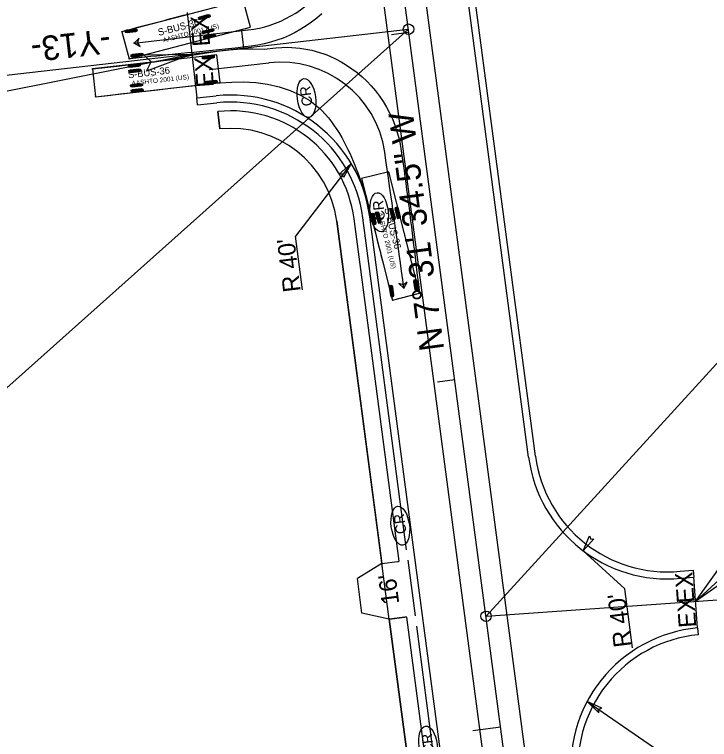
# Model space of a CAD drawing. Extents: x 2367848 to 2369479, y 800728 to 808616.
# Drawn here: x 2368456 to 2368654.5, y 806311.1 to 806518.1 of the extents above; entities that cross this region are included whole.
import ezdxf

# ---------------------------------------------------------------- set-up
doc = ezdxf.new("R2010")
doc.units = 0
for name, color, linetype in [('Prop AutoTurn Projected Path', 7, 'Continuous'), ('Prop AutoTurn Simulation', 7, 'Continuous'), ('Prop Conc 2ft 6in Curb and Gutter', 7, 'Continuous'), ('Prop Conc 4in Sidewalk', 7, 'Continuous'), ('Prop Conc Drive Radius Type', 7, 'Continuous'), ('Prop Conc Driveway', 7, 'Continuous'), ('Prop Dimension', 7, 'Continuous'), ('Prop EOT', 7, 'Continuous'), ('Prop Horizontal Alignment', 7, 'Continuous'), ('Prop Horizontal Alignment Direction Label', 7, 'Continuous'), ('Prop Horizontal Alignment Station Label', 7, 'Continuous'), ('Prop Horizontal Alignment Tick Large', 7, 'Continuous'), ('Prop Horizontal Alignment Tick Small', 7, 'Continuous'), ('Prop Lane Lines', 7, 'Continuous'), ('Prop Shade Light', 7, 'Continuous'), ('Prop Terminator CELL', 7, 'Continuous'), ('Prop WCC CELL', 7, 'Continuous'), ('Prop WCR CELL', 7, 'Continuous')]:
    doc.layers.add(name, color=color, linetype=linetype)

# ---------------------------------------------------------------- blocks, each defined once
blk = doc.blocks.new('CR')
at = {"layer": 'Prop WCC CELL'}
blk.add_ellipse((0.02, -0.02), major_axis=(5.61, 0), ratio=0.462467, dxfattribs=at)
blk.add_text('CR', height=3, dxfattribs=at).set_placement((-2.34, -1.5))

msp = doc.modelspace()

# ---------------------------------------------------------------- linework, layer by layer
at = {"layer": 'Prop AutoTurn Projected Path'}
for p, q in [((2368490.13, 806509.94), (2368522.7, 806513.66)), ((2368511.76, 806502.35), (2368528.64, 806504.28))]:
    msp.add_line(p, q, dxfattribs=at)
for centre, radius, start, end in [((2368519.07, 806545.46), 32, 276.5258, 9.3013), ((2368532.05, 806474.47), 30, 8.2571, 96.5258), ((2364614.09, 805905.9), 3989, 7.69347, 8.25707)]:
    msp.add_arc(centre, radius, start, end, dxfattribs=at)
at = {"layer": 'Prop AutoTurn Simulation'}
for p, q in [((2368521.32, 806522.25), (2368486.69, 806513.17)), ((2368523.35, 806514.51), (2368521.32, 806522.25)), ((2368508.54, 806517.13), (2368511.76, 806517.98)), ((2368508.59, 806516.93), (2368511.81, 806517.78)), ((2368508.64, 806516.73), (2368511.87, 806517.58)), ((2368487.6, 806513.44), (2368490.91, 806513.81)), ((2368488.72, 806505.43), (2368523.35, 806514.51)), ((2368509.59, 806513.1), (2368512.82, 806513.95)), ((2368486.69, 806513.17), (2368488.72, 806505.43)), ((2368487.62, 806513.23), (2368490.93, 806513.6)), ((2368487.64, 806513.02), (2368490.96, 806513.39)), ((2368509.65, 806512.9), (2368512.87, 806513.75)), ((2368509.7, 806512.7), (2368512.92, 806513.55)), ((2368509.97, 806511.65), (2368513.2, 806512.5)), ((2368510.03, 806511.45), (2368513.25, 806512.3)), ((2368510.08, 806511.25), (2368513.3, 806512.09)), ((2368513.79, 806506.61), (2368478.22, 806502.54)), ((2368489.3, 806506.47), (2368492.61, 806506.86)), ((2368489.32, 806506.27), (2368492.63, 806506.66)), ((2368489.35, 806506.06), (2368492.66, 806506.45)), ((2368512.99, 806506.3), (2368509.68, 806505.93)), ((2368513.01, 806506.1), (2368509.7, 806505.72)), ((2368513.03, 806505.89), (2368509.72, 806505.51)), ((2368514.7, 806498.66), (2368513.79, 806506.61)), ((2368513.79, 806506.61), (2368513.79, 806506.61)), ((2368491.83, 806503.88), (2368488.51, 806503.5)), ((2368491.85, 806503.68), (2368488.54, 806503.3)), ((2368491.87, 806503.47), (2368488.56, 806503.09)), ((2368488.72, 806505.43), (2368488.72, 806505.43)), ((2368478.22, 806502.54), (2368479.13, 806494.59)), ((2368492, 806502.39), (2368488.68, 806502.01)), ((2368492.02, 806502.19), (2368488.71, 806501.81)), ((2368492.04, 806501.98), (2368488.73, 806501.6)), ((2368479.13, 806494.59), (2368514.7, 806498.66)), ((2368492.47, 806498.25), (2368489.16, 806497.87)), ((2368492.49, 806498.05), (2368489.18, 806497.67)), ((2368492.52, 806497.84), (2368489.2, 806497.46)), ((2368513.8, 806499.18), (2368510.49, 806498.81)), ((2368513.83, 806498.98), (2368510.51, 806498.6)), ((2368513.85, 806498.77), (2368510.54, 806498.39)), ((2368492.64, 806496.76), (2368489.33, 806496.38)), ((2368492.66, 806496.56), (2368489.35, 806496.18)), ((2368492.69, 806496.35), (2368489.38, 806495.97)), ((2368562.88, 806473.18), (2368555.13, 806471.22)), ((2368571.68, 806438.48), (2368562.88, 806473.18)), ((2368555.13, 806471.22), (2368563.92, 806436.52)), ((2368564.18, 806459.41), (2368563.36, 806462.65)), ((2368564.38, 806459.47), (2368563.56, 806462.7)), ((2368564.58, 806459.52), (2368563.77, 806462.75)), ((2368565.63, 806459.78), (2368564.82, 806463.01)), ((2368565.84, 806459.83), (2368565.02, 806463.07)), ((2368566.04, 806459.89), (2368565.22, 806463.12)), ((2368558.69, 806458.02), (2368557.87, 806461.25)), ((2368558.89, 806458.07), (2368558.07, 806461.3)), ((2368559.09, 806458.12), (2368558.27, 806461.36)), ((2368560.14, 806458.39), (2368559.32, 806461.62)), ((2368560.34, 806458.44), (2368559.52, 806461.67)), ((2368560.55, 806458.49), (2368559.73, 806461.72)), ((2368570.69, 806439.08), (2368570.24, 806442.38)), ((2368570.9, 806439.11), (2368570.44, 806442.41)), ((2368571.1, 806439.13), (2368570.65, 806442.44)), ((2368563.72, 806437.41), (2368563.28, 806440.71)), ((2368563.92, 806437.44), (2368563.48, 806440.74)), ((2368564.13, 806437.46), (2368563.69, 806440.77)), ((2368563.92, 806436.52), (2368571.68, 806438.48)), ((2368571.68, 806438.48), (2368571.68, 806438.48))]:
    msp.add_line(p, q, dxfattribs=at)
for points in [[(2368505.55, 806518.12), (2368504.14, 806517.75), (2368502.71, 806517.37), (2368501.27, 806516.99), (2368499.8, 806516.61), (2368498.32, 806516.22), (2368496.82, 806515.83), (2368495.31, 806515.43), (2368493.79, 806515.03), (2368492.26, 806514.63), (2368490.73, 806514.23), (2368489.18, 806513.83), (2368487.63, 806513.42), (2368486.69, 806513.17)], [(2368543.74, 806518.27), (2368542.33, 806517.05), (2368540.86, 806515.91), (2368539.33, 806514.84), (2368537.75, 806513.85), (2368536.11, 806512.94), (2368534.43, 806512.11), (2368532.7, 806511.37), (2368530.94, 806510.72), (2368529.14, 806510.16), (2368527.32, 806509.69), (2368525.47, 806509.31), (2368523.6, 806509.03), (2368521.73, 806508.81), (2368519.87, 806508.59), (2368518.02, 806508.39), (2368516.19, 806508.19), (2368514.36, 806508), (2368512.55, 806507.81), (2368510.75, 806507.63), (2368508.96, 806507.45), (2368507.17, 806507.27), (2368505.4, 806507.1), (2368503.63, 806506.92), (2368501.88, 806506.75), (2368500.13, 806506.58), (2368498.38, 806506.4), (2368496.65, 806506.23), (2368494.91, 806506.06), (2368493.19, 806505.89), (2368491.47, 806505.71), (2368489.75, 806505.54), (2368488.72, 806505.43)], [(2368478.22, 806502.54), (2368481.78, 806502.94), (2368485.34, 806503.35), (2368488.89, 806503.76), (2368492.45, 806504.16), (2368496.01, 806504.58), (2368499.55, 806505.12), (2368503.09, 806505.75), (2368506.64, 806506.44), (2368510.22, 806507.04), (2368513.83, 806507.6), (2368513.83, 806507.6), (2368517.27, 806507.97), (2368520.71, 806508.25), (2368524.07, 806508.27), (2368527.3, 806508.15), (2368530.67, 806508.54), (2368534.05, 806508.71), (2368537.49, 806508.49), (2368540.94, 806507.86), (2368544.35, 806506.83), (2368544.68, 806506.71)], [(2368544.68, 806506.71), (2368546.02, 806506.17), (2368547.66, 806505.42), (2368549.27, 806504.57), (2368550.84, 806503.63), (2368552.36, 806502.61), (2368553.82, 806501.5), (2368555.24, 806500.31), (2368556.58, 806499.03), (2368557.87, 806497.69), (2368559.08, 806496.27), (2368560.21, 806494.78), (2368561.26, 806493.23), (2368562.23, 806491.63), (2368563.12, 806489.97), (2368563.91, 806488.26), (2368564.61, 806486.5), (2368565.21, 806484.71), (2368565.72, 806482.89), (2368566.13, 806481.04), (2368566.44, 806479.16), (2368566.72, 806477.3), (2368566.99, 806475.44), (2368567.25, 806473.59), (2368567.5, 806471.76), (2368567.75, 806469.94), (2368567.99, 806468.12), (2368568.22, 806466.32), (2368568.45, 806464.53), (2368568.67, 806462.75), (2368568.89, 806460.97), (2368569.11, 806459.21), (2368569.33, 806457.45), (2368569.55, 806455.7), (2368569.76, 806453.95), (2368569.98, 806452.22), (2368570.19, 806450.48), (2368570.4, 806448.76), (2368570.62, 806447.03), (2368570.83, 806445.32), (2368571.04, 806443.6), (2368571.25, 806441.89), (2368571.47, 806440.19), (2368571.68, 806438.48)], [(2368479.13, 806494.59), (2368482.69, 806495), (2368486.25, 806495.4), (2368489.8, 806495.81), (2368493.36, 806496.22), (2368496.92, 806496.62), (2368500.47, 806497.03), (2368504.03, 806497.44), (2368507.59, 806497.84), (2368511.14, 806498.24), (2368514.71, 806498.57), (2368514.71, 806498.57), (2368514.71, 806498.57), (2368518.1, 806498.77), (2368521.5, 806498.81), (2368524.89, 806498.63), (2368528.26, 806498.19), (2368531.57, 806497.45), (2368534.71, 806496.42), (2368537.63, 806495.09), (2368540.3, 806493.49), (2368542.68, 806491.65), (2368542.9, 806491.45)], [(2368542.9, 806491.45), (2368543.75, 806490.65), (2368544.74, 806489.61), (2368545.67, 806488.54), (2368546.53, 806487.44), (2368547.33, 806486.33), (2368548.08, 806485.21), (2368548.79, 806484.08), (2368549.45, 806482.96), (2368550.07, 806481.83), (2368550.66, 806480.7), (2368551.22, 806479.57), (2368551.75, 806478.45), (2368552.25, 806477.33), (2368552.73, 806476.22), (2368553.18, 806475.11), (2368553.61, 806474.01), (2368554.03, 806472.91), (2368554.42, 806471.82), (2368554.81, 806470.73), (2368555.17, 806469.65), (2368555.54, 806468.51), (2368555.92, 806467.33), (2368556.29, 806466.09), (2368556.67, 806464.82), (2368557.04, 806463.5), (2368557.41, 806462.15), (2368557.77, 806460.77), (2368558.13, 806459.36), (2368558.5, 806457.93), (2368558.86, 806456.48), (2368559.24, 806455), (2368559.61, 806453.52), (2368559.99, 806452.02), (2368560.38, 806450.51), (2368560.76, 806448.98), (2368561.15, 806447.45), (2368561.54, 806445.91), (2368561.94, 806444.36), (2368562.33, 806442.8), (2368562.73, 806441.24), (2368563.12, 806439.67), (2368563.52, 806438.09), (2368563.92, 806436.52)]]:
    msp.add_lwpolyline(points, dxfattribs=at)
for points in [[(2368508.66, 806516.68), (2368508.52, 806517.18), (2368508.94, 806517.45), (2368511.26, 806518.06), (2368511.75, 806518.03), (2368511.88, 806517.53), (2368511.47, 806517.26), (2368509.15, 806516.65)], [(2368487.65, 806512.97), (2368487.59, 806513.49), (2368488.04, 806513.7), (2368490.42, 806513.96), (2368490.9, 806513.86), (2368490.96, 806513.34), (2368490.52, 806513.13), (2368488.13, 806512.87)], [(2368509.71, 806512.65), (2368509.58, 806513.15), (2368509.99, 806513.42), (2368512.31, 806514.03), (2368512.8, 806514), (2368512.94, 806513.5), (2368512.52, 806513.23), (2368510.2, 806512.62)], [(2368510.09, 806511.2), (2368509.96, 806511.7), (2368510.37, 806511.97), (2368512.69, 806512.58), (2368513.18, 806512.55), (2368513.32, 806512.04), (2368512.9, 806511.77), (2368510.58, 806511.17)], [(2368490.13, 806509.94), (2368491.84, 806508.91), (2368491.12, 806510.05), (2368491.56, 806511.33)], [(2368489.35, 806506.01), (2368489.29, 806506.53), (2368489.74, 806506.74), (2368492.12, 806507.01), (2368492.6, 806506.91), (2368492.66, 806506.4), (2368492.22, 806506.19), (2368489.83, 806505.91)], [(2368512.98, 806506.36), (2368513.04, 806505.84), (2368512.59, 806505.63), (2368510.21, 806505.36), (2368509.73, 806505.46), (2368509.67, 806505.98), (2368510.12, 806506.19), (2368512.5, 806506.46)], [(2368491.82, 806503.94), (2368491.88, 806503.42), (2368491.43, 806503.21), (2368489.05, 806502.94), (2368488.57, 806503.04), (2368488.51, 806503.56), (2368488.95, 806503.76), (2368491.34, 806504.04)], [(2368491.99, 806502.44), (2368492.05, 806501.93), (2368491.6, 806501.72), (2368489.22, 806501.45), (2368488.74, 806501.55), (2368488.68, 806502.07), (2368489.12, 806502.27), (2368491.51, 806502.55)], [(2368513.8, 806499.24), (2368513.85, 806498.72), (2368513.41, 806498.51), (2368511.02, 806498.24), (2368510.54, 806498.34), (2368510.48, 806498.86), (2368510.93, 806499.07), (2368513.31, 806499.34)], [(2368492.46, 806498.31), (2368492.52, 806497.79), (2368492.08, 806497.58), (2368489.69, 806497.31), (2368489.21, 806497.41), (2368489.15, 806497.93), (2368489.6, 806498.13), (2368491.98, 806498.41)], [(2368492.63, 806496.81), (2368492.69, 806496.3), (2368492.25, 806496.09), (2368489.86, 806495.82), (2368489.38, 806495.92), (2368489.32, 806496.44), (2368489.77, 806496.64), (2368492.15, 806496.92)], [(2368564.63, 806459.53), (2368564.13, 806459.4), (2368563.86, 806459.82), (2368563.27, 806462.14), (2368563.31, 806462.63), (2368563.82, 806462.76), (2368564.08, 806462.35), (2368564.67, 806460.02)], [(2368566.09, 806459.9), (2368565.58, 806459.77), (2368565.32, 806460.18), (2368564.73, 806462.51), (2368564.77, 806463), (2368565.27, 806463.13), (2368565.54, 806462.72), (2368566.13, 806460.39)], [(2368559.14, 806458.14), (2368558.64, 806458.01), (2368558.37, 806458.42), (2368557.78, 806460.75), (2368557.82, 806461.24), (2368558.32, 806461.37), (2368558.59, 806460.95), (2368559.18, 806458.63)], [(2368560.6, 806458.51), (2368560.09, 806458.38), (2368559.82, 806458.79), (2368559.24, 806461.12), (2368559.27, 806461.61), (2368559.78, 806461.74), (2368560.04, 806461.32), (2368560.63, 806459)], [(2368567.19, 806439.92), (2368568.18, 806441.66), (2368567.05, 806440.91), (2368565.77, 806441.33)], [(2368571.15, 806439.14), (2368570.64, 806439.07), (2368570.42, 806439.51), (2368570.09, 806441.89), (2368570.18, 806442.37), (2368570.7, 806442.44), (2368570.92, 806442), (2368571.24, 806439.62)], [(2368564.18, 806437.47), (2368563.67, 806437.4), (2368563.45, 806437.84), (2368563.13, 806440.22), (2368563.23, 806440.71), (2368563.74, 806440.78), (2368563.96, 806440.33), (2368564.28, 806437.95)]]:
    msp.add_lwpolyline(points, close=True, dxfattribs=at)
for centre in [(2368486.69, 806513.17), (2368522.7, 806513.66), (2368522.7, 806513.66), (2368490.13, 806509.94), (2368544.68, 806506.71), (2368544.68, 806506.71), (2368488.72, 806505.43), (2368528.64, 806504.28), (2368528.64, 806504.28), (2368478.22, 806502.54), (2368511.76, 806502.35), (2368479.13, 806494.59), (2368542.9, 806491.45), (2368542.9, 806491.45), (2368561.74, 806478.78), (2368561.74, 806478.78), (2368567.19, 806439.92), (2368571.68, 806438.48), (2368563.92, 806436.52)]:
    msp.add_circle(centre, 0.0417, dxfattribs=at)
at = {"layer": 'Prop Conc 2ft 6in Curb and Gutter'}
for p, q in [((2368604.81, 806391.98), (2368575.97, 806610.21)), ((2368508.26, 806492.28), (2368508.05, 806494.27)), ((2368508.26, 806492.28), (2368513.81, 806492.86)), ((2368567.99, 806365.28), (2368555.47, 806460.05)), ((2368646.09, 806359.12), (2368649.84, 806359.48)), ((2368649.84, 806359.48), (2368650.03, 806357.49)), ((2368579.65, 806277), (2368570.87, 806343.47)), ((2368651.05, 806342.98), (2368651.24, 806340.99))]:
    msp.add_line(p, q, dxfattribs=at)
for centre, start, end in [((2368517.79, 806455.07), 7.5263, 96.0115), ((2368642.48, 806396.95), 187.5263, 275.4541), ((2368654.87, 806303.16), 95.4791, 187.5263)]:
    msp.add_arc(centre, 38, start, end, dxfattribs=at)
at = {"layer": 'Prop Conc 4in Sidewalk'}
for p, q in [((2368514.6, 806485.4), (2368514.08, 806490.38)), ((2368561.11, 806360.08), (2368548.03, 806459.07)), ((2368565.9, 806362.02), (2368552.99, 806459.72)), ((2368567.24, 806348.03), (2368567.24, 806348.03)), ((2368572.61, 806273.05), (2368563.04, 806345.46)), ((2368577.56, 806273.74), (2368568, 806346.07))]:
    msp.add_line(p, q, dxfattribs=at)
for centre, radius, start, end in [((2368517.79, 806455.07), 35.5, 7.5263, 96.0115), ((2368517.79, 806455.07), 30.5, 7.5263, 96.0115), ((2368565.01, 806364.89), 3, 277.5638, 287.1532), ((2368567.89, 806343.07), 3, 87.9064, 97.5263)]:
    msp.add_arc(centre, radius, start, end, dxfattribs=at)
at = {"layer": 'Prop Conc Drive Radius Type'}
msp.add_line((2368570.48, 806346.44), (2368568.38, 806362.31), dxfattribs=at)
at = {"layer": 'Prop Conc Driveway'}
for p, q in [((2368560.94, 806361.32), (2368553.91, 806357.11)), ((2368560.94, 806361.32), (2368565.41, 806361.91)), ((2368563.04, 806345.46), (2368560.94, 806361.32)), ((2368555.23, 806347.14), (2368553.91, 806357.11)), ((2368563.04, 806345.46), (2368555.23, 806347.14)), ((2368563.04, 806345.46), (2368567.5, 806346.05))]:
    msp.add_line(p, q, dxfattribs=at)
at = {"layer": 'Prop Dimension'}
for p, q in [((2368243.84, 806454.37), (2368506.62, 806506.79)), ((2368552.15, 806475.56), (2368536.27, 806454.83)), ((2368538.23, 806439.48), (2368536.27, 806454.83)), ((2368718.85, 806413.25), (2368650.52, 806350.5)), ((2368618.45, 806364.98), (2368630.33, 806354.11)), ((2368632.48, 806337.25), (2368630.33, 806354.11)), ((2368619.57, 806321.98), (2368638.81, 806308.7))]:
    msp.add_line(p, q, dxfattribs=at)
at = {"layer": 'Prop EOT'}
for p, q in [((2368602.82, 806391.71), (2368573.99, 806609.95)), ((2368505.26, 806518.67), (2368508.05, 806494.27)), ((2368508.05, 806494.27), (2368513.6, 806494.85)), ((2368613.33, 806037.35), (2368557.45, 806460.31)), ((2368646.28, 806357.13), (2368650.03, 806357.49)), ((2368651.05, 806342.98), (2368650.03, 806357.49))]:
    msp.add_line(p, q, dxfattribs=at)
for centre, start, end in [((2368517.79, 806455.07), 7.5263, 96.0115), ((2368642.48, 806396.95), 187.5263, 275.4541), ((2368654.87, 806303.16), 95.4791, 187.5263)]:
    msp.add_arc(centre, 40, start, end, dxfattribs=at)
at = {"layer": 'Prop Horizontal Alignment'}
for p, q in [((2368631.17, 806039.71), (2368556.15, 806607.59)), ((2368322.82, 806485.77), (2368568.53, 806513.87)), ((2368590.67, 806346.28), (2368757.51, 806358.04))]:
    msp.add_line(p, q, dxfattribs=at)
at = {"layer": 'Prop Horizontal Alignment Station Label'}
for p, q in [((2368568.53, 806513.87), (2368361.71, 806329.46)), ((2368590.67, 806346.28), (2368694.22, 806459.7))]:
    msp.add_line(p, q, dxfattribs=at)
for centre in [(2368568.53, 806513.87), (2368590.67, 806346.28)]:
    msp.add_circle(centre, 1.5, dxfattribs=at)
at = {"layer": 'Prop Horizontal Alignment Tick Large'}
msp.add_line((2368594.85, 806314.62), (2368586.92, 806313.57), dxfattribs=at)
at = {"layer": 'Prop Horizontal Alignment Tick Small'}
for p, q in [((2368521.52, 806508.5), (2368520.96, 806513.46)), ((2368568.66, 806512.9), (2368563.7, 806512.24)), ((2368581.76, 806413.76), (2368576.8, 806413.1))]:
    msp.add_line(p, q, dxfattribs=at)
at = {"layer": 'Prop Lane Lines'}
for p, q in [((2368637.12, 806040.49), (2368562.1, 806608.37)), ((2368625.23, 806038.92), (2368550.2, 806606.8))]:
    msp.add_line(p, q, dxfattribs=at)
at = {"layer": 'Prop Shade Light'}
for p, q in [((2368514.08, 806490.38), (2368514.6, 806485.4)), ((2368548.03, 806459.07), (2368560.94, 806361.32)), ((2368565.9, 806362.02), (2368552.99, 806459.72)), ((2368560.94, 806361.32), (2368565.41, 806361.91)), ((2368567.5, 806346.05), (2368563.04, 806345.46)), ((2368563.04, 806345.46), (2368572.61, 806273.05)), ((2368577.56, 806273.74), (2368568, 806346.07))]:
    msp.add_line(p, q, dxfattribs=at)
for centre, radius, start, end in [((2368517.79, 806455.07), 35.5, 7.5263, 96.0115), ((2368517.79, 806455.07), 30.5, 7.5263, 96.0115), ((2368565.01, 806364.89), 3, 277.5638, 287.1532), ((2368567.89, 806343.07), 3, 87.9064, 97.5263)]:
    msp.add_arc(centre, radius, start, end, dxfattribs=at)
at = {"layer": 'Prop Terminator CELL'}
for points in [[(2368492.92, 806506.56), (2368506.62, 806506.79), (2368493.73, 806501.91), (2368494.98, 806504.59)], [(2368548.75, 806472.51), (2368552.15, 806475.56), (2368549.97, 806471.52), (2368549.7, 806472.47)], [(2368621.5, 806368.37), (2368618.45, 806364.98), (2368620.18, 806369.23), (2368620.55, 806368.32)], [(2368661.73, 806358.37), (2368650.52, 806350.5), (2368658.46, 806361.77), (2368658.92, 806358.86)], [(2368623.72, 806320.06), (2368619.57, 806321.98), (2368622.84, 806318.75), (2368622.82, 806319.73)]]:
    msp.add_lwpolyline(points, close=True, dxfattribs=at)

# ---------------------------------------------------------------- block references
at = {"layer": 'Prop WCR CELL'}
for p, rotation in [((2368539.35, 806494.22), 97.54241161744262), ((2368560.12, 806461.6), 96.16491816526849), ((2368566.17, 806372.1), 97.54241161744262), ((2368574.11, 806309.34), 97.54241161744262)]:
    msp.add_blockref('CR', p, dxfattribs=dict(at, rotation=rotation))

# ---------------------------------------------------------------- texts
at = {"layer": 'Prop AutoTurn Simulation'}
for s, height, rotation, p in [('S-BUS-36', 2, 14.6891, (2368497.24, 806511.97)), ('AASHTO 2001 (US)', 1.3333, 14.6891, (2368498.55, 806510.07)), ('(c) 2014 Transoft Solutions, Inc. All rights reserved.', 0.08, 14.6891, (2368503.46, 806513.39)), ('S-BUS-36', 2, 6.5258, (2368488.5, 806499.85)), ('AASHTO 2001 (US)', 1.3333, 6.5258, (2368489.52, 806497.78)), ('(c) 2014 Transoft Solutions, Inc. All rights reserved.', 0.08, 6.5258, (2368494.85, 806500.37)), ('S-BUS-36', 2, 284.2225, (2368561.59, 806462.64)), ('AASHTO 2001 (US)', 1.3333, 284.2225, (2368559.69, 806461.35)), ('(c) 2014 Transoft Solutions, Inc. All rights reserved.', 0.08, 284.2225, (2368562.96, 806456.42))]:
    msp.add_text(s, height=height, rotation=rotation, dxfattribs=at).set_placement(p)
at = {"layer": 'Prop Dimension'}
for s, rotation, p in [('EX', 94.0321, (2368511.87, 806509.12)), ('EX', 94.0321, (2368512.95, 806497.44)), ("R 40'", 97.0147, (2368537.75, 806439.12)), ('EX', 94.0321, (2368650.21, 806350.19)), ("16'", 97.5263, (2368565.9, 806349.94)), ("R 40'", 97.0626, (2368632.17, 806337.73)), ('EX', 94.0321, (2368650.73, 806343.2))]:
    msp.add_text(s, height=5, rotation=rotation, dxfattribs=at).set_placement(p)
at = {"layer": 'Prop Horizontal Alignment Direction Label'}
msp.add_text('N 7%%d 31\' 34.5" W', height=7, rotation=97.5263, dxfattribs=at).set_placement((2368578.72, 806422.49))
at = {"layer": 'Prop Horizontal Alignment Station Label'}
msp.add_text('-Y13-', height=7, rotation=186.5258, dxfattribs=at).set_placement((2368483.07, 806514.04))

doc.saveas('drawing.dxf')
